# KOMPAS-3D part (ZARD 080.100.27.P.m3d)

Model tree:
1. Плоскость под углом:1
     Угол = -15
2. Булева операция:1
3. Булева операция:2
4. Булева операция:3
5. Булева операция:4
6. Булева операция:5
7. Булева операция:6
8. Булева операция:31
9. Булева операция:32
10. Булева операция:33
11. Булева операция:34
12. Булева операция:35
13. Булева операция:36
14. Булева операция:37
15. Булева операция:38
16. Булева операция:39
17. Булева операция:40
18. Булева операция:41
19. Булева операция:42
20. Булева операция:43
21. Булева операция:44
22. Булева операция:45
23. Булева операция:46
24. Булева операция:47
25. Булева операция:48
26. Булева операция:49
27. Булева операция:50
28. Булева операция:51
29. Булева операция:52
30. Булева операция:53
31. Булева операция:54  (labels: C:\Program Files\ASCON\KOMPAS-3D V13\Sys\graphic.lyt)

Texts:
  ЗАРД 080.100.27-ХХ.Р
  Кран шаровой фланцевый
  ООО "ИК Энерпред-Ярдос"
